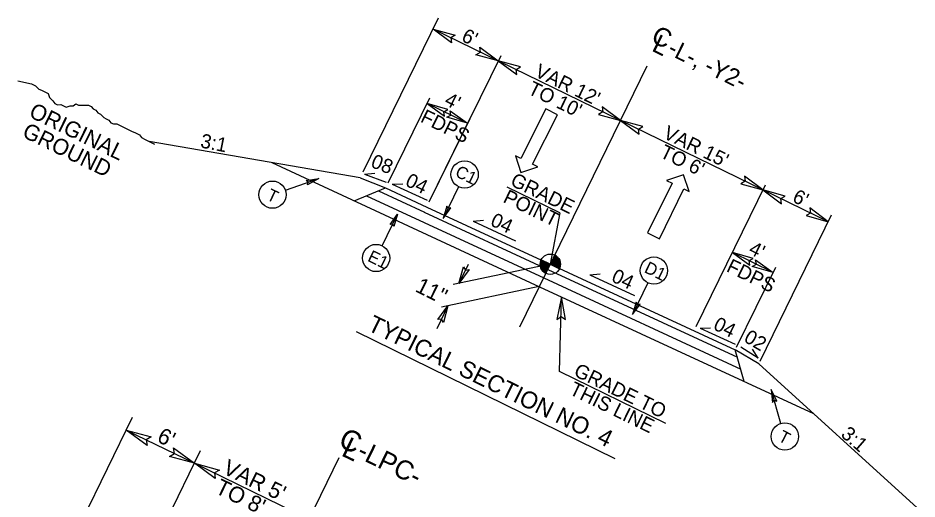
# Model space of a CAD drawing. Extents: x 1518247 to 1523638, y 635234 to 639927.
# Drawn here: x 1520686 to 1521318, y 637050 to 637388 of the extents above; entities that cross this region are included whole.
import ezdxf

# ---------------------------------------------------------------- set-up
doc = ezdxf.new("R2010")
doc.units = 0
for name, color, linetype in [('Prop Dimension', 7, 'Continuous'), ('Prop Dimension Text', 7, 'Continuous'), ('Prop Lane Arrow CELL', 7, 'Continuous'), ('Prop Shade Light', 7, 'Continuous'), ('Typical Arrow Superelevation CELL', 7, 'Continuous'), ('Typical Grade Point Symbol CELL', 7, 'Continuous'), ('Typical Hinge Slope Interstate CELL', 7, 'Continuous'), ('Typical ID Circle CELL', 7, 'Continuous'), ('Typical Pavement Slope CELL', 7, 'Continuous'), ('Typical Pavement Slope Information CELL', 7, 'Continuous'), ('Typical Shoulder Slope CELL', 7, 'Continuous'), ('Typical Shoulder Slope Information CELL', 7, 'Continuous'), ('Typical Text Centerline CELL', 7, 'Continuous'), ('Typical Text General CELL', 7, 'Continuous'), ('Typical Text Grade Point CELL', 7, 'Continuous'), ('Typical Text ID Circle CELL', 7, 'Continuous'), ('Typical Text Label CELL', 7, 'Continuous')]:
    doc.layers.add(name, color=color, linetype=linetype)

# ---------------------------------------------------------------- blocks, each defined once
blk = doc.blocks.new('TERMINATOR')
at = {"layer": 'Prop Shade Light'}
blk.add_lwpolyline([(-0.469, 0.081), (0, 0), (-0.471, -0.083), (-0.411, 0)], close=True, dxfattribs=at)

msp = doc.modelspace()

# ---------------------------------------------------------------- linework, layer by layer
at = {"layer": 'Prop Dimension'}
for p, q in [((1520928.27, 637279.72), (1520981.27, 637387.89)), ((1521109.22, 637315.8), (1520977.47, 637380.12)), ((1520974.81, 637258.52), (1521025.27, 637361.5)), ((1520945.88, 637271.97), (1520975.12, 637331.65)), ((1521001.79, 637313.8), (1520973.22, 637327.76)), ((1520974.81, 637258.53), (1521003.54, 637317.39)), ((1521255.23, 637244.52), (1521109.22, 637315.8)), ((1521162.34, 637170.85), (1521211, 637270.53)), ((1521066.61, 637250.92), (1521059.86, 637214.69)), ((1521207.23, 637146.48), (1521257.51, 637249.49)), ((1521216.45, 637208.99), (1521187.78, 637222.98)), ((1521059.86, 637214.69), (1520991.69, 637200.42)), ((1521002.12, 637214.6), (1520995.59, 637201.24)), ((1521190.71, 637156.28), (1521218.2, 637212.57)), ((1521052.13, 637198.97), (1520983.46, 637184.6)), ((1521066.29, 637139.24), (1521067.77, 637191.76)), ((1520987.93, 637185.53), (1520980.02, 637169.34)), ((1521141.07, 637102.73), (1521066.29, 637139.24)), ((1520709.56, 636990.51), (1520766.27, 637107.05)), ((1520761.91, 637098.08), (1520809.82, 637074.76)), ((1520757.21, 636966.63), (1520814.19, 637083.73)), ((1520809.82, 637074.76), (1520890.47, 637035.52))]:
    msp.add_line(p, q, dxfattribs=at)
at = {"layer": 'Prop Lane Arrow CELL'}
for p, q in [((1521056.78, 637324.02), (1521039.13, 637289.16)), ((1521047.35, 637285), (1521065, 637319.86)), ((1521065, 637319.86), (1521056.78, 637324.02)), ((1521039.13, 637289.16), (1521035.4, 637291.05)), ((1521035.4, 637291.05), (1521039.15, 637279.29)), ((1521039.15, 637279.29), (1521051.09, 637283.11)), ((1521051.09, 637283.11), (1521047.35, 637285)), ((1521153.49, 637277.62), (1521141.6, 637273.64)), ((1521157.41, 637265.92), (1521153.49, 637277.62)), ((1521145.37, 637271.8), (1521128.22, 637236.68)), ((1521141.6, 637273.64), (1521145.37, 637271.8)), ((1521136.5, 637232.64), (1521153.64, 637267.76)), ((1521153.64, 637267.76), (1521157.41, 637265.92)), ((1521128.22, 637236.68), (1521136.5, 637232.64))]:
    msp.add_line(p, q, dxfattribs=at)
at = {"layer": 'Prop Shade Light'}
for points in [[(1520888.23, 637273.54), (1520897.11, 637275.05), (1520889.22, 637270.6), (1520889.76, 637272.46)], [(1520987.11, 637255.61), (1520984.59, 637246.96), (1520989.93, 637254.29), (1520988.01, 637253.96)], [(1520947.26, 637242.64), (1520952.54, 637249.94), (1520950.03, 637241.23), (1520949.11, 637242.94)], [(1521120.11, 637188.01), (1521117.59, 637179.36), (1521122.92, 637186.69), (1521121.01, 637186.36)], [(1521218.94, 637118.47), (1521214.98, 637126.56), (1521215.97, 637117.55), (1521217.16, 637119.08)]]:
    msp.add_lwpolyline(points, close=True, dxfattribs=at)
at = {"layer": 'Typical Arrow Superelevation CELL'}
for p, q in [((1520929.38, 637278.07), (1520936.64, 637278.71)), ((1520929.38, 637278.07), (1520944.58, 637272.47)), ((1520948.86, 637271.12), (1520956.15, 637271.18)), ((1520948.86, 637271.12), (1520973.31, 637259.84)), ((1521165.21, 637169.83), (1521172.51, 637169.89)), ((1521165.21, 637169.83), (1521189.66, 637158.55)), ((1521205.85, 637148.77), (1521193.77, 637156.3)), ((1521205.85, 637148.77), (1521201.9, 637154.9))]:
    msp.add_line(p, q, dxfattribs=at)
at = {"layer": 'Typical Grade Point Symbol CELL'}
for p, q in [((1521059.86, 637214.69), (1521053.45, 637217.82)), ((1521063, 637221.11), (1521059.86, 637214.69)), ((1521056.73, 637208.28), (1521059.86, 637214.69)), ((1521066.29, 637211.58), (1521059.86, 637214.69)), ((1521059.86, 637214.69), (1521066.29, 637211.58))]:
    msp.add_line(p, q, dxfattribs=at)
for points in [[(1521053.31, 637217.5), (1521059.71, 637214.38)], [(1521053.36, 637217.64), (1521059.77, 637214.51)], [(1521053.42, 637217.77), (1521053.42, 637217.77), (1521059.84, 637214.64)], [(1521061.23, 637217.49), (1521067, 637214.67)], [(1521061.29, 637217.62), (1521067.01, 637214.82)], [(1521061.35, 637217.74), (1521067, 637214.99)], [(1521061.42, 637217.87), (1521066.99, 637215.15)], [(1521061.48, 637218), (1521066.98, 637215.31)], [(1521061.54, 637218.13), (1521066.96, 637215.48)], [(1521061.6, 637218.26), (1521066.94, 637215.65)], [(1521061.67, 637218.39), (1521066.91, 637215.82)], [(1521061.73, 637218.51), (1521066.89, 637215.99)], [(1521061.79, 637218.64), (1521066.85, 637216.17)], [(1521061.85, 637218.77), (1521066.82, 637216.35)], [(1521061.92, 637218.9), (1521066.76, 637216.53)], [(1521061.98, 637219.03), (1521066.71, 637216.72)], [(1521062.04, 637219.15), (1521066.66, 637216.9)], [(1521062.11, 637219.28), (1521066.6, 637217.09)], [(1521062.17, 637219.41), (1521066.52, 637217.29)], [(1521062.23, 637219.54), (1521066.44, 637217.49)], [(1521062.29, 637219.67), (1521066.34, 637217.69)], [(1521062.36, 637219.8), (1521066.25, 637217.9)], [(1521062.42, 637219.92), (1521066.14, 637218.11)], [(1521062.48, 637220.05), (1521066.02, 637218.33)], [(1521062.54, 637220.18), (1521065.88, 637218.55)], [(1521062.61, 637220.31), (1521065.71, 637218.79)], [(1521062.67, 637220.44), (1521065.53, 637219.04)], [(1521062.73, 637220.57), (1521065.33, 637219.3)], [(1521062.79, 637220.69), (1521065.09, 637219.57)], [(1521062.86, 637220.82), (1521064.77, 637219.89)], [(1521062.92, 637220.95), (1521064.37, 637220.24)], [(1521062.98, 637221.08), (1521063.68, 637220.74)], [(1521052.73, 637214.77), (1521058.52, 637211.94)], [(1521052.73, 637214.61), (1521058.46, 637211.81)], [(1521052.74, 637215.08), (1521058.65, 637212.2)], [(1521052.74, 637214.92), (1521058.58, 637212.07)], [(1521052.74, 637214.45), (1521058.4, 637211.68)], [(1521052.74, 637214.29), (1521058.33, 637211.56)], [(1521052.75, 637215.24), (1521058.71, 637212.33)], [(1521052.75, 637214.12), (1521058.27, 637211.43)], [(1521052.76, 637215.39), (1521058.77, 637212.45)], [(1521052.76, 637213.96), (1521058.21, 637211.3)], [(1521052.78, 637215.54), (1521058.83, 637212.58)], [(1521052.78, 637213.79), (1521058.15, 637211.17)], [(1521052.8, 637215.69), (1521058.9, 637212.71)], [(1521052.81, 637213.62), (1521058.08, 637211.04)], [(1521052.82, 637215.84), (1521058.96, 637212.84)], [(1521052.84, 637213.44), (1521058.02, 637210.91)], [(1521052.85, 637215.98), (1521059.02, 637212.97)], [(1521052.87, 637216.13), (1521059.08, 637213.1)], [(1521052.87, 637213.27), (1521057.96, 637210.79)], [(1521052.9, 637216.27), (1521059.15, 637213.22)], [(1521052.91, 637213.09), (1521057.89, 637210.66)], [(1521052.94, 637216.41), (1521059.21, 637213.35)], [(1521052.96, 637212.91), (1521057.83, 637210.53)], [(1521052.97, 637216.56), (1521059.27, 637213.48)], [(1521053.01, 637216.7), (1521059.34, 637213.61)], [(1521053.01, 637212.73), (1521057.77, 637210.4)], [(1521053.05, 637216.83), (1521059.4, 637213.74)], [(1521053.06, 637212.54), (1521057.71, 637210.27)], [(1521053.1, 637216.97), (1521059.46, 637213.87)], [(1521053.13, 637212.35), (1521057.64, 637210.15)], [(1521053.15, 637217.11), (1521059.52, 637213.99)], [(1521053.19, 637212.16), (1521057.58, 637210.02)], [(1521053.2, 637217.24), (1521059.59, 637214.12)], [(1521053.25, 637217.38), (1521059.65, 637214.25)], [(1521053.27, 637211.96), (1521057.52, 637209.89)], [(1521053.36, 637211.76), (1521057.46, 637209.76)], [(1521053.46, 637211.55), (1521057.39, 637209.63)], [(1521053.57, 637211.34), (1521057.33, 637209.5)], [(1521053.69, 637211.12), (1521057.27, 637209.37)], [(1521059.91, 637214.79), (1521066.33, 637211.66), (1521066.33, 637211.66)], [(1521059.98, 637214.92), (1521066.39, 637211.79)], [(1521060.04, 637215.05), (1521066.44, 637211.92)], [(1521060.1, 637215.18), (1521066.5, 637212.05)], [(1521060.16, 637215.31), (1521066.55, 637212.19)], [(1521060.23, 637215.43), (1521066.6, 637212.32)], [(1521060.29, 637215.56), (1521066.65, 637212.46)], [(1521060.35, 637215.69), (1521066.68, 637212.6)], [(1521060.41, 637215.82), (1521066.73, 637212.74)], [(1521060.48, 637215.95), (1521066.76, 637212.88)], [(1521060.54, 637216.08), (1521066.8, 637213.02)], [(1521060.6, 637216.2), (1521066.83, 637213.16)], [(1521060.66, 637216.33), (1521066.87, 637213.3)], [(1521060.73, 637216.46), (1521066.89, 637213.45)], [(1521060.79, 637216.59), (1521066.92, 637213.6)], [(1521060.85, 637216.72), (1521066.94, 637213.75)], [(1521060.92, 637216.85), (1521066.96, 637213.89)], [(1521060.98, 637216.97), (1521066.98, 637214.04)], [(1521061.04, 637217.1), (1521066.99, 637214.2)], [(1521061.1, 637217.23), (1521066.99, 637214.36)], [(1521061.17, 637217.36), (1521067, 637214.51)], [(1521053.83, 637210.9), (1521057.21, 637209.25)], [(1521053.98, 637210.66), (1521057.14, 637209.12)], [(1521054.14, 637210.42), (1521057.08, 637208.99)], [(1521054.35, 637210.16), (1521057.02, 637208.86)], [(1521054.59, 637209.89), (1521056.96, 637208.73)], [(1521054.88, 637209.59), (1521056.89, 637208.61)], [(1521055.26, 637209.24), (1521056.83, 637208.48)], [(1521055.85, 637208.79), (1521056.77, 637208.35)]]:
    msp.add_lwpolyline(points, dxfattribs=at)
msp.add_circle((1521059.87, 637214.7), 7.14, dxfattribs=at)
for start, end in [(153.98879, 243.98879), (333.98879, 63.98879)]:
    msp.add_arc((1521059.87, 637214.7), 7.14, start, end, dxfattribs=at)
at = {"layer": 'Typical Hinge Slope Interstate CELL'}
for p, q in [((1520926.16, 637275.41), (1520778.11, 637301.07)), ((1521206.35, 637144.6), (1521317.5, 637043.48))]:
    msp.add_line(p, q, dxfattribs=at)
msp.add_lwpolyline([(1520685.85, 637343.78), (1520695.44, 637341.57), (1520698.23, 637340.2), (1520700.56, 637337.92), (1520702.42, 637337.01), (1520705.21, 637335.64), (1520707.06, 637334.73), (1520708.01, 637331.96), (1520710.34, 637329.66), (1520711.74, 637327.82), (1520713.6, 637326.91), (1520715.92, 637326.93), (1520717.77, 637326.02), (1520719.63, 637325.11), (1520722.4, 637326.06), (1520724.71, 637326.08), (1520726.55, 637327.48), (1520728.41, 637326.57), (1520730.72, 637326.59), (1520733.04, 637326.61), (1520735.35, 637326.63), (1520737.21, 637325.72), (1520738.61, 637323.88), (1520740.46, 637322.97), (1520741.87, 637321.13), (1520743.72, 637320.22), (1520746.06, 637317.93), (1520747.92, 637317.02), (1520749.77, 637316.11), (1520751.17, 637314.26), (1520753.03, 637313.35), (1520755.35, 637313.38), (1520757.2, 637312.47), (1520759.06, 637311.56), (1520760.92, 637310.65), (1520762.77, 637309.74), (1520765.56, 637308.37), (1520768.35, 637307.01), (1520771.14, 637305.64), (1520772.54, 637303.8), (1520775.32, 637302.43), (1520778.11, 637301.07), (1520781.82, 637299.25)], dxfattribs=at)
at = {"layer": 'Typical ID Circle CELL'}
for p, q in [((1520873.75, 637266.81), (1520897.11, 637275.05)), ((1520995.46, 637269.22), (1520984.59, 637246.96)), ((1520941.64, 637227.69), (1520952.54, 637249.94)), ((1521128.46, 637201.63), (1521117.59, 637179.36)), ((1521221.92, 637102.77), (1521214.98, 637126.56))]:
    msp.add_line(p, q, dxfattribs=at)
for centre in [(1520999.67, 637277.84), (1520864.71, 637263.63), (1520937.42, 637219.08), (1521132.66, 637210.24), (1521224.61, 637093.57)]:
    msp.add_circle(centre, 9.59, dxfattribs=at)
at = {"layer": 'Typical Pavement Slope CELL'}
for p, q in [((1520864.2, 637286.15), (1521052.31, 637198.93)), ((1520921.99, 637259.35), (1520944.13, 637268.39)), ((1520930.62, 637262.87), (1521055.2, 637205.11)), ((1520971.31, 637251.36), (1521058.19, 637211.08)), ((1520973.06, 637254.94), (1521059.86, 637214.69)), ((1521059.86, 637214.69), (1521189.85, 637154.42)), ((1521055.2, 637205.11), (1521193.64, 637140.93)), ((1521058.19, 637211.08), (1521191.27, 637149.37)), ((1521052.31, 637198.93), (1521244.66, 637109.74)), ((1521196.06, 637132.28), (1521189.85, 637154.42))]:
    msp.add_line(p, q, dxfattribs=at)
at = {"layer": 'Typical Pavement Slope Information CELL'}
for p, q in [((1521005.66, 637244.99), (1521012.92, 637245.64)), ((1521005.66, 637244.99), (1521035.29, 637231.25)), ((1521087.66, 637207.23), (1521094.93, 637207.88)), ((1521087.66, 637207.23), (1521118.89, 637192.75))]:
    msp.add_line(p, q, dxfattribs=at)
for points in [[(1520987.78, 637323.49), (1520973.22, 637327.76), (1520985.55, 637318.75), (1520985.01, 637321.98)], [(1520989.49, 637322.7), (1521001.79, 637313.8), (1520987.12, 637318.03), (1520990, 637319.58)], [(1521202.36, 637218.73), (1521187.78, 637222.98), (1521200.13, 637213.99), (1521199.58, 637217.22)], [(1521204.13, 637217.87), (1521216.45, 637208.99), (1521201.76, 637213.2), (1521204.65, 637214.75)]]:
    msp.add_lwpolyline(points, close=True, dxfattribs=at)
at = {"layer": 'Typical Shoulder Slope CELL'}
for p, q in [((1520926.16, 637275.41), (1520944.13, 637268.39)), ((1520944.13, 637268.39), (1520973.06, 637254.94)), ((1520939.09, 637266.33), (1520971.38, 637251.33)), ((1521206.35, 637144.6), (1521189.85, 637154.42))]:
    msp.add_line(p, q, dxfattribs=at)
at = {"layer": 'Typical Text Centerline CELL'}
for p, q in [((1521038.44, 637170.8), (1521127.97, 637354.2)), ((1520811.07, 636872.36), (1520911.49, 637078.72))]:
    msp.add_line(p, q, dxfattribs=at)
at = {"layer": 'Typical Text Grade Point CELL'}
msp.add_line((1521066.61, 637250.92), (1521029.63, 637268.97), dxfattribs=at)
at = {"layer": 'Typical Text Label CELL'}
msp.add_line((1520923.37, 637167.3), (1521105.27, 637078.17), dxfattribs=at)

# ---------------------------------------------------------------- block references
at = {"layer": 'Prop Dimension'}
for p, xscale, yscale, rotation in [((1520977.47, 637380.12), 33.82820784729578, 36.41552511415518, 153.89617982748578), ((1521023.26, 637357.77), 33.82820784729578, 36.41552511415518, -26.103820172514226), ((1521023.26, 637357.77), 33.82820784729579, -36.41552511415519, 153.97926941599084), ((1521109.22, 637315.8), 33.82820784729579, -36.41552511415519, -26.020730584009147), ((1521109.22, 637315.8), 33.82820784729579, -36.41552511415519, 153.97926941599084), ((1521209.25, 637266.94), 33.82820784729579, -36.41552511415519, -26.020730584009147), ((1521209.25, 637266.94), 33.82820784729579, -36.41552511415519, 153.97926941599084), ((1521255.1, 637244.56), 33.82820784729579, -36.41552511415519, -26.020730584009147), ((1520995.59, 637201.24), 25.371155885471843, 27.311643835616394, -116.02073058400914), ((1520987.93, 637185.53), 25.371155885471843, 27.311643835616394, 63.979269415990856), ((1521067.77, 637191.76), 33.8282078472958, -36.415525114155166, 89.05083957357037), ((1520761.91, 637098.08), 38.04253472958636, 40.95218065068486, 154.05109588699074), ((1520809.82, 637074.76), 38.04253472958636, 40.95218065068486, -25.94890411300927), ((1520809.82, 637074.76), 38.04253472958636, 40.95218065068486, 154.05109588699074)]:
    msp.add_blockref('TERMINATOR', p, dxfattribs=dict(at, xscale=xscale, yscale=yscale, rotation=rotation))

# ---------------------------------------------------------------- texts
for s, height, rotation, p in [("6'", 9.969, 333.89618, (1520996.75, 637372.08)), ("VAR 12' ", 9.969, 333.97927, (1521048.15, 637347.16)), ("TO 10'", 9.969, 333.97927, (1521043.36, 637334.96)), ('FDPS', 9.969, 333.89618, (1520967.94, 637315.14)), ("VAR 15'", 9.969, 333.97927, (1521138.44, 637303.77)), ("TO 6'", 9.969, 333.97927, (1521136.12, 637290.36)), ("6'", 9.969, 333.97927, (1521229.26, 637259.04)), ('FDPS', 9.969, 333.97927, (1521182.9, 637210.03)), ('11"', 11.189, 333.71146, (1520964.24, 637195.88)), ("6'", 11.211, 334.0511, (1520782.78, 637090.3)), ("VAR 5' ", 11.211, 334.0511, (1520828.96, 637067.9)), ("TO 8'", 11.211, 334.0511, (1520823.59, 637054.18))]:
    msp.add_text(s, height=height, rotation=rotation, dxfattribs=at).set_placement(p)
at = {"layer": 'Prop Dimension Text'}
for s, height, rotation, p in [('-L-, -Y2-', 11.962, 333.89618, (1521141.48, 637362.84)), ('TYPICAL SECTION NO. 4', 11.9625, 333.89618, (1520930.69, 637168.63)), ('-LPC-', 13.453, 334.0511, (1520923.19, 637079.26))]:
    msp.add_text(s, height=height, rotation=rotation, dxfattribs=at).set_placement(p)
at = {"layer": 'Typical Hinge Slope Interstate CELL'}
for s, height, rotation, p in [('ORIGINAL', 11.211, 334.0511, (1520692.79, 637318.7)), ('GROUND', 11.211, 334.0511, (1520688.06, 637304.66)), ('3:1', 9.969, 348.88604, (1520813.52, 637296.92)), ('3:1', 9.969, 318.98941, (1521263.37, 637094.13))]:
    msp.add_text(s, height=height, rotation=rotation, dxfattribs=at).set_placement(p)
at = {"layer": 'Typical Pavement Slope Information CELL'}
for s, rotation, p in [("4'", 333.89618, (1520984.71, 637327.18)), ('04', 335.12501, (1521017.07, 637242.27)), ("4'", 333.97927, (1521198.53, 637222.47)), ('04', 335.12501, (1521102.09, 637202.93))]:
    msp.add_text(s, height=9.969, rotation=rotation, dxfattribs=at).set_placement(p)
at = {"layer": 'Typical Shoulder Slope Information CELL'}
for s, rotation, p in [('08', 338.65723, (1520933.08, 637283.25)), ('04', 334.10328, (1520957.28, 637270.3)), ('04', 334.10328, (1521173.67, 637169.25)), ('02', 329.21822, (1521195.13, 637160.79))]:
    msp.add_text(s, height=9.969, rotation=rotation, dxfattribs=at).set_placement(p)
at = {"layer": 'Typical Text Centerline CELL'}
for s, height, rotation, p in [('L', 13.09, 334.03237, (1521130.42, 637365.04)), ('C', 13.08, 333.97927, (1521129.84, 637371.36)), ('C', 14.71, 334.0511, (1520910.04, 637087.16)), ('L', 14.72, 333.998, (1520912.24, 637080.5))]:
    msp.add_text(s, height=height, rotation=rotation, dxfattribs=at).set_placement(p)
at = {"layer": 'Typical Text General CELL'}
for s, p in [('GRADE TO', (1521075.62, 637136.63)), ('THIS LINE', (1521072.49, 637123.62))]:
    msp.add_text(s, height=9.969, rotation=333.97927, dxfattribs=at).set_placement(p)
at = {"layer": 'Typical Text Grade Point CELL'}
for s, p in [('GRADE', (1521031.07, 637270.56)), ('POINT', (1521025.97, 637258.7))]:
    msp.add_text(s, height=9.969, rotation=333.97927, dxfattribs=at).set_placement(p)
at = {"layer": 'Typical Text ID Circle CELL'}
for s, height, rotation, p in [('C1', 8.581, 333.97927, (1520992.34, 637276.91)), ('T', 8.58, 334.77303, (1520859.89, 637260.43)), ('E1', 8.581, 333.89618, (1520930.82, 637217.28)), ('D1', 8.581, 333.97927, (1521125.23, 637209.36)), ('T', 8.58, 332.37619, (1521219.31, 637090.83))]:
    msp.add_text(s, height=height, rotation=rotation, dxfattribs=at).set_placement(p)

doc.saveas('drawing.dxf')
